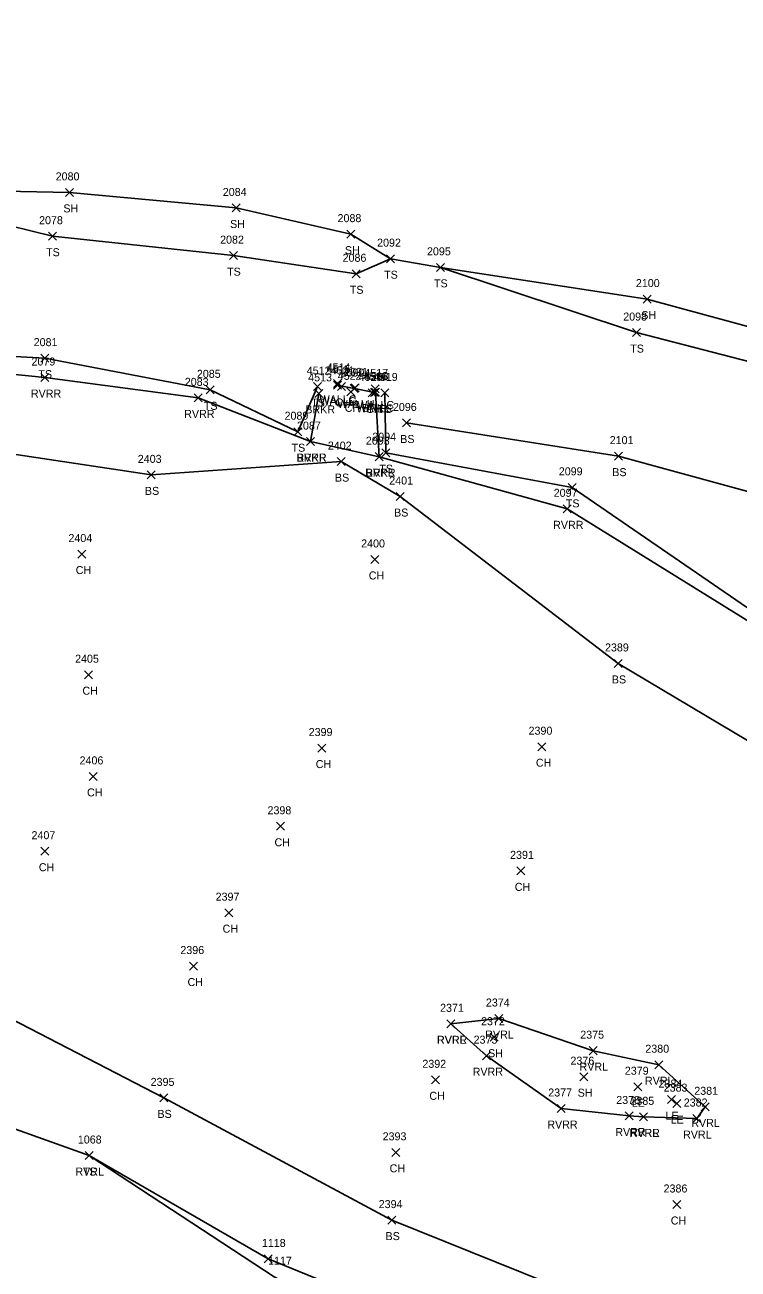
# Model space of a CAD drawing. Extents: x 1509053 to 1511576, y 400838 to 402572.
# Drawn here: x 1509252.1 to 1509430.5, y 402256.5 to 402567.4 of the extents above; entities that cross this region are included whole.
import ezdxf

# ---------------------------------------------------------------- set-up
doc = ezdxf.new("R2010")
doc.units = 0
for name, color, linetype in [('D_A', 7, 'Continuous'), ('D_I', 7, 'Continuous'), ('D_TIC', 7, 'Continuous'), ('L_A', 7, 'Continuous'), ('L_I', 7, 'Continuous'), ('L_TIC', 7, 'Continuous'), ('LAWE', 7, 'Continuous'), ('LELB', 7, 'Continuous'), ('LSOGP', 7, 'Continuous'), ('LW', 7, 'Continuous')]:
    doc.layers.add(name, color=color, linetype=linetype)

msp = doc.modelspace()

# ---------------------------------------------------------------- linework, layer by layer
at = {"layer": 'D_TIC'}
for points in [[(1509333.49, 402475.52), (1509335.49, 402477.52)], [(1509335.49, 402475.52), (1509333.49, 402477.52)], [(1509333.73, 402475.69), (1509335.73, 402477.69)], [(1509335.73, 402475.69), (1509333.73, 402477.69)]]:
    msp.add_lwpolyline(points, dxfattribs=at)
at = {"layer": 'L_TIC'}
for points in [[(1509262.28, 402524.53), (1509264.28, 402526.53)], [(1509264.28, 402524.53), (1509262.28, 402526.53)], [(1509303.97, 402520.64), (1509305.97, 402522.64)], [(1509305.97, 402520.64), (1509303.97, 402522.64)], [(1509258.04, 402513.58), (1509260.04, 402515.58)], [(1509260.04, 402513.58), (1509258.04, 402515.58)], [(1509332.66, 402514.1), (1509334.66, 402516.1)], [(1509334.66, 402514.1), (1509332.66, 402516.1)], [(1509303.29, 402508.73), (1509305.29, 402510.73)], [(1509305.29, 402508.73), (1509303.29, 402510.73)], [(1509342.55, 402507.97), (1509344.55, 402509.97)], [(1509344.55, 402507.97), (1509342.55, 402509.97)], [(1509333.97, 402504.2), (1509335.97, 402506.2)], [(1509335.97, 402504.2), (1509333.97, 402506.2)], [(1509355.02, 402505.81), (1509357.02, 402507.81)], [(1509357.02, 402505.81), (1509355.02, 402507.81)], [(1509406.76, 402497.88), (1509408.76, 402499.88)], [(1509408.76, 402497.88), (1509406.76, 402499.88)], [(1509404.08, 402489.51), (1509406.08, 402491.51)], [(1509406.08, 402489.51), (1509404.08, 402491.51)], [(1509256.12, 402483.12), (1509258.12, 402485.12)], [(1509258.12, 402483.12), (1509256.12, 402485.12)], [(1509256.15, 402478.28), (1509258.15, 402480.28)], [(1509258.15, 402478.28), (1509256.15, 402480.28)], [(1509297.49, 402475.21), (1509299.49, 402477.21)], [(1509299.49, 402475.21), (1509297.49, 402477.21)], [(1509324.31, 402476.02), (1509326.31, 402478.02)], [(1509326.31, 402476.02), (1509324.31, 402478.02)], [(1509329.28, 402476.81), (1509331.28, 402478.81)], [(1509331.28, 402476.81), (1509329.28, 402478.81)], [(1509329.29, 402476.36), (1509331.29, 402478.36)], [(1509331.29, 402476.36), (1509329.29, 402478.36)], [(1509330.29, 402476.05), (1509332.29, 402478.05)], [(1509332.29, 402476.05), (1509330.29, 402478.05)], [(1509338.71, 402475.43), (1509340.71, 402477.43)], [(1509340.71, 402475.43), (1509338.71, 402477.43)], [(1509294.46, 402473.2), (1509296.46, 402475.2)], [(1509296.46, 402473.2), (1509294.46, 402475.2)], [(1509324.67, 402474.32), (1509326.67, 402476.32)], [(1509326.67, 402474.32), (1509324.67, 402476.32)], [(1509332.63, 402474.71), (1509334.63, 402476.71)], [(1509334.63, 402474.71), (1509332.63, 402476.71)], [(1509337.95, 402474.45), (1509339.95, 402476.45)], [(1509339.95, 402474.45), (1509337.95, 402476.45)], [(1509338.55, 402474.57), (1509340.55, 402476.57)], [(1509340.55, 402474.57), (1509338.55, 402476.57)], [(1509338.79, 402474.64), (1509340.79, 402476.64)], [(1509340.79, 402474.64), (1509338.79, 402476.64)], [(1509341.1, 402474.43), (1509343.1, 402476.43)], [(1509343.1, 402474.43), (1509341.1, 402476.43)], [(1509346.55, 402466.93), (1509348.55, 402468.93)], [(1509348.55, 402466.93), (1509346.55, 402468.93)], [(1509319.41, 402464.74), (1509321.41, 402466.74)], [(1509321.41, 402464.74), (1509319.41, 402466.74)], [(1509322.52, 402462.27), (1509324.52, 402464.27)], [(1509324.52, 402462.27), (1509322.52, 402464.27)], [(1509322.52, 402462.27), (1509324.52, 402464.27)], [(1509324.52, 402462.27), (1509322.52, 402464.27)], [(1509341.35, 402459.5), (1509343.35, 402461.5)], [(1509343.35, 402459.5), (1509341.35, 402461.5)], [(1509330.23, 402457.28), (1509332.23, 402459.28)], [(1509332.23, 402457.28), (1509330.23, 402459.28)], [(1509339.74, 402458.51), (1509341.74, 402460.51)], [(1509341.74, 402458.51), (1509339.74, 402460.51)], [(1509339.74, 402458.51), (1509341.74, 402460.51)], [(1509341.74, 402458.51), (1509339.74, 402460.51)], [(1509399.56, 402458.64), (1509401.56, 402460.64)], [(1509401.56, 402458.64), (1509399.56, 402460.64)], [(1509282.72, 402453.96), (1509284.72, 402455.96)], [(1509284.72, 402453.96), (1509282.72, 402455.96)], [(1509387.98, 402450.84), (1509389.98, 402452.84)], [(1509389.98, 402450.84), (1509387.98, 402452.84)], [(1509345.01, 402448.55), (1509347.01, 402450.55)], [(1509347.01, 402448.55), (1509345.01, 402450.55)], [(1509386.7, 402445.48), (1509388.7, 402447.48)], [(1509388.7, 402445.48), (1509386.7, 402447.48)], [(1509265.38, 402434.18), (1509267.38, 402436.18)], [(1509267.38, 402434.18), (1509265.38, 402436.18)], [(1509338.64, 402432.83), (1509340.64, 402434.83)], [(1509340.64, 402432.83), (1509338.64, 402434.83)], [(1509399.45, 402406.85), (1509401.45, 402408.85)], [(1509401.45, 402406.85), (1509399.45, 402408.85)], [(1509267.04, 402404.04), (1509269.04, 402406.04)], [(1509269.04, 402404.04), (1509267.04, 402406.04)], [(1509325.37, 402385.71), (1509327.37, 402387.71)], [(1509327.37, 402385.71), (1509325.37, 402387.71)], [(1509380.42, 402386.05), (1509382.42, 402388.05)], [(1509382.42, 402386.05), (1509380.42, 402388.05)], [(1509268.21, 402378.63), (1509270.21, 402380.63)], [(1509270.21, 402378.63), (1509268.21, 402380.63)], [(1509315.07, 402366.17), (1509317.07, 402368.17)], [(1509317.07, 402366.17), (1509315.07, 402368.17)], [(1509256.15, 402359.94), (1509258.15, 402361.94)], [(1509258.15, 402359.94), (1509256.15, 402361.94)], [(1509375.14, 402355.03), (1509377.14, 402357.03)], [(1509377.14, 402355.03), (1509375.14, 402357.03)], [(1509302.1, 402344.58), (1509304.1, 402346.58)], [(1509304.1, 402344.58), (1509302.1, 402346.58)], [(1509293.33, 402331.25), (1509295.33, 402333.25)], [(1509295.33, 402331.25), (1509293.33, 402333.25)], [(1509357.64, 402316.82), (1509359.64, 402318.82)], [(1509359.64, 402316.82), (1509357.64, 402318.82)], [(1509357.64, 402316.82), (1509359.64, 402318.82)], [(1509359.64, 402316.82), (1509357.64, 402318.82)], [(1509369.67, 402318.14), (1509371.67, 402320.14)], [(1509371.67, 402318.14), (1509369.67, 402320.14)], [(1509368.46, 402313.46), (1509370.46, 402315.46)], [(1509370.46, 402313.46), (1509368.46, 402315.46)], [(1509393.25, 402310.11), (1509395.25, 402312.11)], [(1509395.25, 402310.11), (1509393.25, 402312.11)], [(1509366.59, 402308.86), (1509368.59, 402310.86)], [(1509368.59, 402308.86), (1509366.59, 402310.86)], [(1509409.6, 402306.6), (1509411.6, 402308.6)], [(1509411.6, 402306.6), (1509409.6, 402308.6)], [(1509353.78, 402302.83), (1509355.78, 402304.83)], [(1509355.78, 402302.83), (1509353.78, 402304.83)], [(1509390.85, 402303.61), (1509392.85, 402305.61)], [(1509392.85, 402303.61), (1509390.85, 402305.61)], [(1509404.41, 402301.1), (1509406.41, 402303.1)], [(1509406.41, 402301.1), (1509404.41, 402303.1)], [(1509285.85, 402298.31), (1509287.85, 402300.31)], [(1509287.85, 402298.31), (1509285.85, 402300.31)], [(1509412.84, 402297.88), (1509414.84, 402299.88)], [(1509414.84, 402297.88), (1509412.84, 402299.88)], [(1509385.25, 402295.66), (1509387.25, 402297.66)], [(1509387.25, 402295.66), (1509385.25, 402297.66)], [(1509414.11, 402296.88), (1509416.11, 402298.88)], [(1509416.11, 402296.88), (1509414.11, 402298.88)], [(1509421.19, 402296.08), (1509423.19, 402298.08)], [(1509423.19, 402296.08), (1509421.19, 402298.08)], [(1509402.25, 402293.79), (1509404.25, 402295.79)], [(1509404.25, 402293.79), (1509402.25, 402295.79)], [(1509405.8, 402293.58), (1509407.8, 402295.58)], [(1509407.8, 402293.58), (1509405.8, 402295.58)], [(1509405.8, 402293.58), (1509407.8, 402295.58)], [(1509407.8, 402293.58), (1509405.8, 402295.58)], [(1509419.13, 402293.16), (1509421.13, 402295.16)], [(1509421.13, 402293.16), (1509419.13, 402295.16)], [(1509267.21, 402283.91), (1509269.21, 402285.91)], [(1509269.21, 402283.91), (1509267.21, 402285.91)], [(1509267.21, 402283.91), (1509269.21, 402285.91)], [(1509269.21, 402283.91), (1509267.21, 402285.91)], [(1509343.85, 402284.71), (1509345.85, 402286.71)], [(1509345.85, 402284.71), (1509343.85, 402286.71)], [(1509414.15, 402271.68), (1509416.15, 402273.68)], [(1509416.15, 402271.68), (1509414.15, 402273.68)], [(1509342.87, 402267.78), (1509344.87, 402269.78)], [(1509344.87, 402267.78), (1509342.87, 402269.78)], [(1509311.96, 402258.07), (1509313.96, 402260.07)], [(1509313.96, 402258.07), (1509311.96, 402260.07)]]:
    msp.add_lwpolyline(points, dxfattribs=at)
at = {"layer": 'LAWE'}
for points in [[(1509123.74, 402492.84), (1509257.15, 402479.28), (1509295.46, 402474.2), (1509323.52, 402463.27), (1509340.74, 402459.51), (1509387.7, 402446.48), (1509437.74, 402415.48), (1509460.68, 402397.47), (1509520.56, 402367.88), (1509582.65, 402355.05), (1509635.23, 402334.07), (1509671.33, 402306.45), (1509693.48, 402289.28), (1509731.88, 402256.56), (1509764.07, 402209.44), (1509800.56, 402171.69), (1509807.78, 402147.71), (1509842.98, 402079.8), (1509863.82, 402015.71), (1509885.9, 401967.01)], [(1509323.52, 402463.27), (1509325.67, 402475.32)], [(1509340.74, 402459.51), (1509339.79, 402475.64)], [(1509105.87, 402324.24), (1509166.85, 402316.84), (1509211.49, 402305.13), (1509268.21, 402284.91), (1509312.96, 402259.07), (1509356.2, 402241.45), (1509401.11, 402232.66), (1509452.56, 402212.8), (1509514.16, 402192.04), (1509556.38, 402176.06), (1509631.87, 402126.97), (1509661.73, 402089.31), (1509701.86, 402034.14), (1509721.26, 402000.81), (1509742.13, 401921.74), (1509766.75, 401859.14), (1509782.51, 401819.75), (1509797.91, 401768.02), (1509814.1, 401723.17), (1509831.98, 401671.21)], [(1509358.64, 402317.82), (1509370.67, 402319.14), (1509394.25, 402311.11), (1509410.6, 402307.6), (1509422.19, 402297.08), (1509420.13, 402294.16), (1509406.8, 402294.58)], [(1509358.64, 402317.82), (1509367.58, 402309.86), (1509386.25, 402296.66), (1509403.25, 402294.79), (1509406.8, 402294.58)]]:
    msp.add_lwpolyline(points, dxfattribs=at)
at = {"layer": 'LELB'}
for points in [[(1509115.54, 402530), (1509210.25, 402526.55), (1509259.04, 402514.59), (1509304.29, 402509.73), (1509334.97, 402505.2), (1509343.55, 402508.97), (1509356.02, 402506.81), (1509405.08, 402490.51), (1509457.58, 402476.95), (1509474.2, 402464.72), (1509479.41, 402463.89), (1509501.59, 402438.85), (1509538.87, 402419.67), (1509601.4, 402398.68), (1509663.58, 402377.9), (1509703.97, 402366.5), (1509741.81, 402353.02), (1509786.94, 402318.01), (1509829.53, 402284.86)], [(1509123.32, 402495.56), (1509210.35, 402486.66), (1509257.12, 402484.12), (1509298.49, 402476.21), (1509320.42, 402465.74)], [(1509325.31, 402477.02), (1509320.42, 402465.74)], [(1509342.1, 402475.43), (1509342.35, 402460.5)], [(1510159.39, 401957.43), (1510109.97, 401933.78), (1510073.83, 401925.83), (1510030.04, 401920.72), (1509978.38, 401922.31), (1509938.9, 401925.26), (1509910.2, 401929.61), (1509860.63, 401969.45), (1509838.12, 402012.73), (1509801.23, 402094.39), (1509783.45, 402152.2), (1509742.56, 402227.61), (1509676.33, 402272.85), (1509632.84, 402314.37), (1509578.95, 402339.23), (1509514.2, 402355.92), (1509451.14, 402377.68), (1509400.45, 402407.85), (1509346.01, 402449.55), (1509331.23, 402458.28), (1509283.72, 402454.96), (1509188.27, 402469.29), (1509186.96, 402469.12), (1509142.12, 402468.65)], [(1509347.55, 402467.93), (1509400.56, 402459.64), (1509444.49, 402447.66), (1509466.55, 402414.51), (1509525.3, 402381.4), (1509586.66, 402368.88), (1509644.11, 402347.26), (1509687.55, 402337.45), (1509716.12, 402320.34), (1509770.15, 402297.9), (1509810.8, 402261.62)], [(1509342.35, 402460.5), (1509388.98, 402451.84), (1509438.42, 402417.91), (1509462.47, 402401.71), (1509520.99, 402370.94), (1509584.16, 402359.65), (1509637.85, 402336.46), (1509671.92, 402311.04), (1509696.29, 402294.18), (1509734.49, 402260.5), (1509774.99, 402220.64)], [(1509893.6, 401622.33), (1509860.64, 401660.7), (1509835.46, 401719.88), (1509820.45, 401775.67), (1509804.55, 401821.18), (1509793.58, 401877.47), (1509769.39, 401921.13), (1509750.31, 401995.31), (1509714.67, 402043.06), (1509675.87, 402101.28), (1509636.96, 402136.16), (1509603.47, 402183.37), (1509565.38, 402200.63), (1509506.19, 402219.72), (1509454.31, 402229.61), (1509409.3, 402242.42), (1509343.87, 402268.78), (1509286.85, 402299.31), (1509229.32, 402329.05), (1509168.38, 402334.88), (1509111.42, 402354.71)], [(1509268.21, 402284.91), (1509314.49, 402254.64), (1509356.98, 402231.85), (1509402.27, 402223.46), (1509451.09, 402207.68), (1509510.53, 402186.04), (1509553.53, 402174.63), (1509629.32, 402126.51), (1509658.3, 402084.82), (1509698.84, 402034.54), (1509720.34, 401997.13), (1509738.81, 401919.7), (1509762.85, 401861.64), (1509780.24, 401817.03), (1509795.72, 401767.1), (1509811.96, 401722.66)]]:
    msp.add_lwpolyline(points, dxfattribs=at)
at = {"layer": 'LSOGP'}
msp.add_lwpolyline([(1509459.59, 402484.75), (1509407.76, 402498.88), (1509356.02, 402506.81), (1509343.55, 402508.97), (1509333.66, 402515.1), (1509304.97, 402521.64), (1509263.28, 402525.53), (1509210.25, 402526.55), (1509146.57, 402567.38), (1509138.45, 402532.93), (1509115.54, 402530), (1509119.17, 402503.18), (1509123.74, 402492.84), (1509142.12, 402468.65), (1509129.34, 402447.08), (1509122.87, 402416.47), (1509118.38, 402385.32), (1509111.42, 402354.71), (1509105.87, 402324.24), (1509106.65, 402313.08), (1509100.33, 402304.48), (1509105.01, 402291.69), (1509099.68, 402257.85), (1509084.77, 402216.15)], dxfattribs=at)
at = {"layer": 'LW'}
msp.add_lwpolyline([(1509330.28, 402477.81), (1509330.29, 402477.36), (1509339.55, 402475.57), (1509339.71, 402476.43)], dxfattribs=at)

# ---------------------------------------------------------------- texts
at = {"layer": 'D_A'}
for s, p in [('WALLH', (1509330.32, 402471.69)), ('P', (1509333.87, 402471.52))]:
    msp.add_text(s, height=2, dxfattribs=at).set_placement(p)
at = {"layer": 'D_I'}
for s, p in [('2090', (1509331.07, 402479.52)), ('2091', (1509331.96, 402479.69))]:
    msp.add_text(s, height=2, dxfattribs=at).set_placement(p)
at = {"layer": 'L_A'}
for s, p in [('SH', (1509261.77, 402520.53)), ('SH', (1509303.46, 402516.64)), ('TS', (1509257.45, 402509.59)), ('SH', (1509332.15, 402510.1)), ('TS', (1509302.7, 402504.73)), ('TS', (1509341.96, 402503.97)), ('TS', (1509333.38, 402500.2)), ('TS', (1509354.43, 402501.81)), ('SH', (1509406.25, 402493.88)), ('TS', (1509403.49, 402485.51)), ('TS', (1509255.53, 402479.12)), ('RVRR', (1509253.66, 402474.28)), ('TS', (1509323.72, 402472.02)), ('WALLC', (1509325.82, 402472.81)), ('WALLC', (1509325.83, 402472.36)), ('CH', (1509329.78, 402472.05)), ('RVRR', (1509291.98, 402469.2)), ('TS', (1509296.9, 402471.21)), ('BRKR', (1509322.26, 402470.32)), ('CH', (1509332.12, 402470.71)), ('WALLC', (1509335.09, 402470.57)), ('WALLC', (1509335.25, 402471.43)), ('BRKL', (1509336.44, 402470.64)), ('CH', (1509337.44, 402470.45)), ('TS', (1509340.51, 402470.43)), ('BS', (1509345.99, 402462.93)), ('TS', (1509318.82, 402460.74)), ('RVRR', (1509320.03, 402458.27)), ('BRKR', (1509320.11, 402458.27)), ('BS', (1509329.67, 402453.28)), ('RVRR', (1509337.25, 402454.51)), ('BRKL', (1509337.38, 402454.51)), ('TS', (1509340.76, 402455.5)), ('BS', (1509399, 402454.64)), ('BS', (1509282.16, 402449.96)), ('TS', (1509387.39, 402446.84)), ('BS', (1509344.45, 402444.55)), ('RVRR', (1509384.21, 402441.48)), ('CH', (1509264.86, 402430.18)), ('CH', (1509338.13, 402428.83)), ('BS', (1509398.89, 402402.85)), ('CH', (1509266.53, 402400.04)), ('CH', (1509324.86, 402381.71)), ('CH', (1509379.91, 402382.05)), ('CH', (1509267.7, 402374.63)), ('CH', (1509314.56, 402362.17)), ('CH', (1509255.64, 402355.94)), ('CH', (1509374.63, 402351.03)), ('CH', (1509301.58, 402340.58)), ('CH', (1509292.82, 402327.25)), ('RVRL', (1509367.24, 402314.14)), ('RVRR', (1509355.15, 402312.82)), ('RVRL', (1509355.21, 402312.82)), ('SH', (1509367.95, 402309.47)), ('RVRR', (1509364.1, 402304.86)), ('RVRL', (1509390.82, 402306.11)), ('RVRL', (1509407.17, 402302.6)), ('CH', (1509353.27, 402298.83)), ('SH', (1509390.34, 402299.61)), ('LE', (1509403.9, 402297.1)), ('BS', (1509285.29, 402294.31)), ('RVRR', (1509382.76, 402291.66)), ('LE', (1509412.33, 402293.88)), ('LE', (1509413.6, 402292.88)), ('RVRL', (1509418.76, 402292.08)), ('RVRR', (1509399.76, 402289.79)), ('RVRR', (1509403.31, 402289.58)), ('RVRL', (1509403.37, 402289.58)), ('RVRL', (1509416.7, 402289.16)), ('RVRL', (1509264.78, 402279.91)), ('TS', (1509266.62, 402279.91)), ('CH', (1509343.34, 402280.71)), ('CH', (1509413.63, 402267.68)), ('BS', (1509342.31, 402263.78))]:
    msp.add_text(s, height=2, dxfattribs=at).set_placement(p)
at = {"layer": 'L_I'}
for s, p in [('2080', (1509259.85, 402528.53)), ('2084', (1509301.63, 402524.64)), ('2078', (1509255.7, 402517.59)), ('2088', (1509330.32, 402518.1)), ('2082', (1509300.96, 402512.73)), ('2092', (1509340.21, 402511.97)), ('2095', (1509352.68, 402509.81)), ('2086', (1509331.58, 402508.2)), ('2100', (1509404.9, 402501.88)), ('2098', (1509401.74, 402493.51)), ('2081', (1509254.35, 402487.12)), ('2079', (1509253.81, 402482.28)), ('2085', (1509295.15, 402479.21)), ('4512', (1509322.62, 402480.02)), ('4513', (1509322.98, 402478.32)), ('4514', (1509327.59, 402480.81)), ('4515', (1509327.6, 402480.36)), ('4521', (1509328.6, 402480.05)), ('4522', (1509330.37, 402478.71)), ('4520', (1509335.6, 402478.45)), ('4516', (1509336.8, 402478.57)), ('4517', (1509337.02, 402479.43)), ('4518', (1509337.1, 402478.64)), ('4519', (1509339.4, 402478.43)), ('2083', (1509292.13, 402477.2)), ('2089', (1509317.07, 402468.74)), ('2096', (1509344.16, 402470.93)), ('2087', (1509320.18, 402466.27)), ('2087', (1509320.18, 402466.27)), ('2093', (1509337.4, 402462.51)), ('2093', (1509337.4, 402462.51)), ('2094', (1509339.01, 402463.5)), ('2101', (1509398.36, 402462.64)), ('2402', (1509327.89, 402461.28)), ('2403', (1509280.38, 402457.96)), ('2099', (1509385.63, 402454.84)), ('2401', (1509343.24, 402452.55)), ('2097', (1509384.36, 402449.48)), ('2404', (1509263.04, 402438.18)), ('2400', (1509336.22, 402436.83)), ('2389', (1509397.18, 402410.85)), ('2405', (1509264.7, 402408.04)), ('2399', (1509323.1, 402389.71)), ('2390', (1509378.07, 402390.05)), ('2406', (1509265.82, 402382.63)), ('2398', (1509312.81, 402370.17)), ('2407', (1509253.81, 402363.94)), ('2391', (1509373.45, 402359.03)), ('2397', (1509299.84, 402348.58)), ('2396', (1509291.02, 402335.25)), ('2371', (1509355.95, 402320.82)), ('2371', (1509355.95, 402320.82)), ('2374', (1509367.41, 402322.14)), ('2372', (1509366.2, 402317.47)), ('2375', (1509390.99, 402314.11)), ('2373', (1509364.33, 402312.86)), ('2380', (1509407.26, 402310.6)), ('2376', (1509388.54, 402307.61)), ('2392', (1509351.52, 402306.83)), ('2379', (1509402.14, 402305.1)), ('2395', (1509283.59, 402302.31)), ('2384', (1509410.58, 402301.88)), ('2383', (1509411.85, 402300.88)), ('2377', (1509382.99, 402299.66)), ('2378', (1509399.99, 402297.79)), ('2385', (1509403.54, 402297.58)), ('2385', (1509403.54, 402297.58)), ('2381', (1509419.5, 402300.08)), ('2382', (1509416.87, 402297.16)), ('2393', (1509341.59, 402288.71)), ('1068', (1509265.39, 402287.91)), ('1068', (1509265.39, 402287.91)), ('2386', (1509411.83, 402275.68)), ('2394', (1509340.61, 402271.78)), ('1118', (1509311.4, 402262.07)), ('1117', (1509312.94, 402257.64))]:
    msp.add_text(s, height=2, dxfattribs=at).set_placement(p)

doc.saveas('drawing.dxf')
